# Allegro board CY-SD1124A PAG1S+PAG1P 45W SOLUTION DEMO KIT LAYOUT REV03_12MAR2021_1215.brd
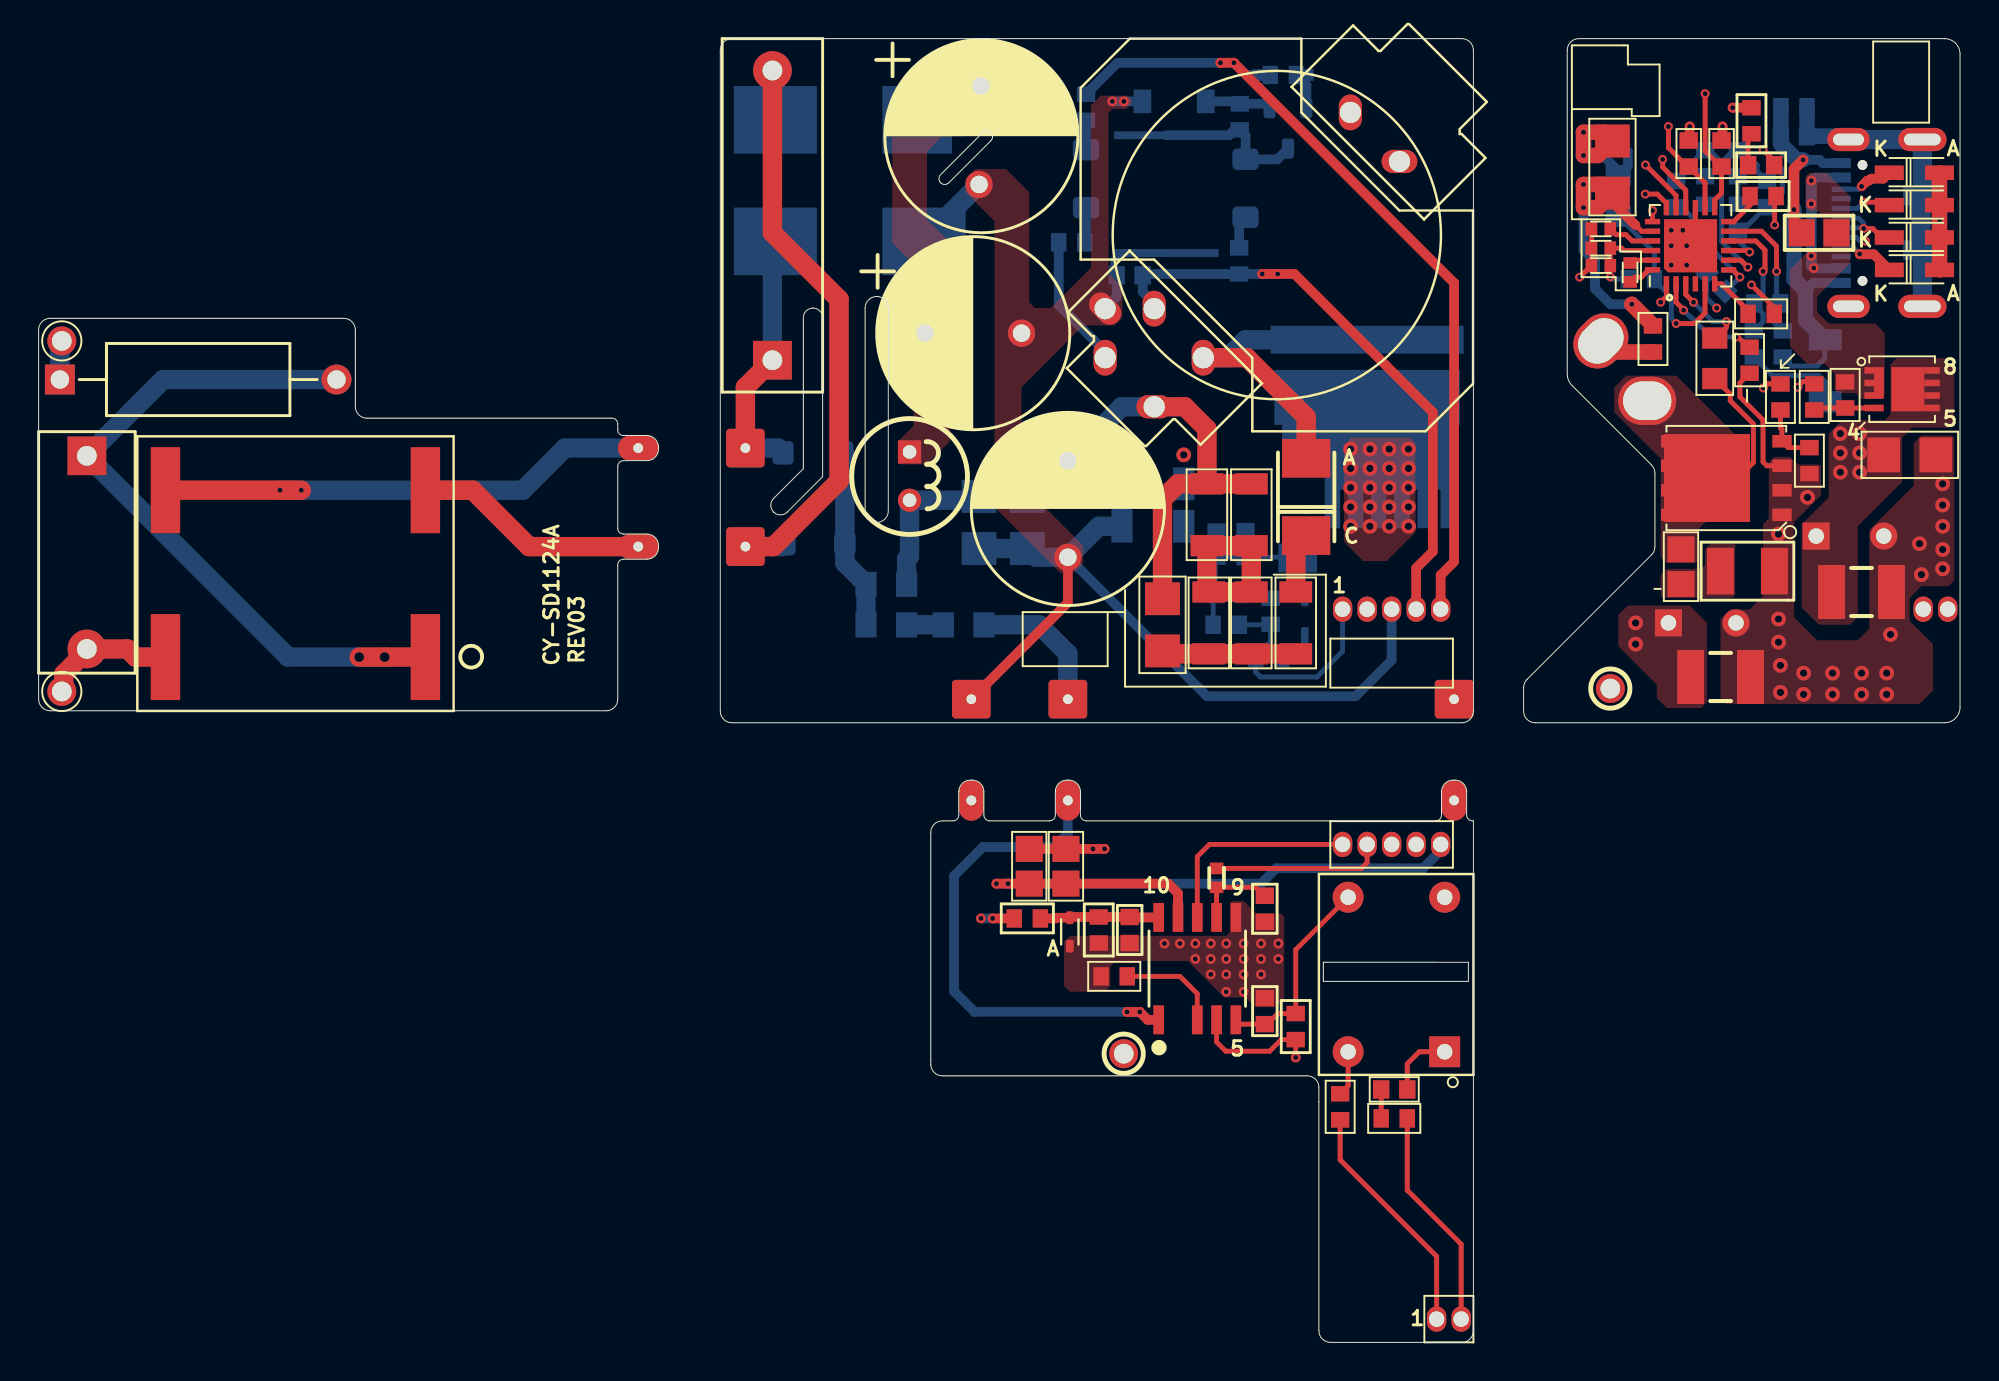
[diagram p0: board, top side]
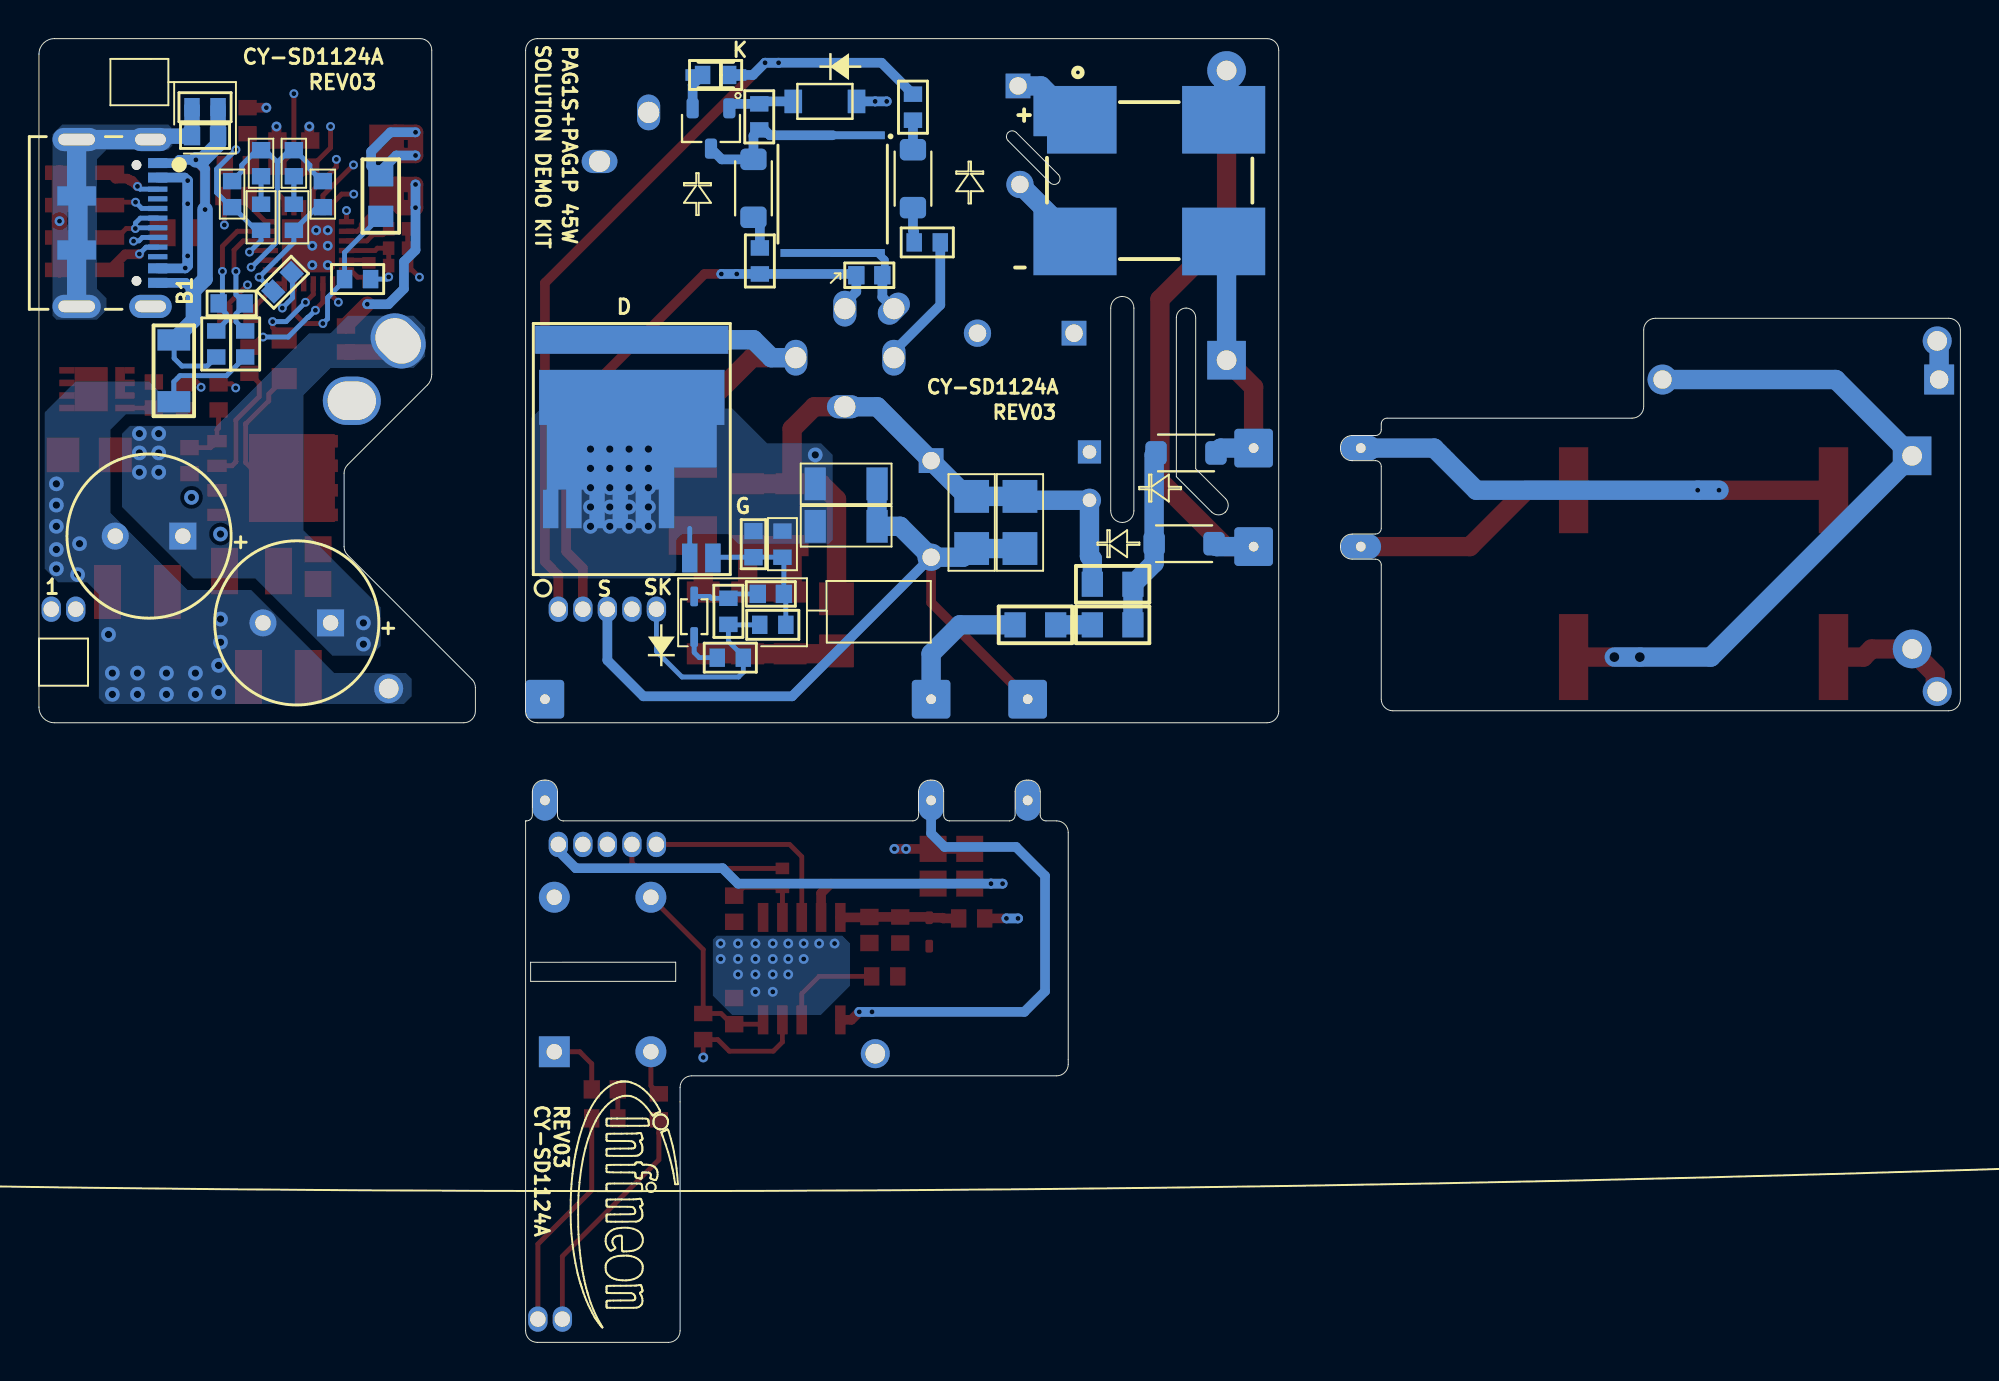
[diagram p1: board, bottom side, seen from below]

Outline 99.5 x 67.5 mm; copper layers: TOP, SIGNAL LAYER 1, SIGNAL LAYER 2, BOTTOM. Coordinates in mm from the lower left corner of the outline.
Outline path: 0,52.42 arc(0.18,52.84) 0.6,53.02 15.8,53.02 arc(16.22,52.84) 16.4,52.42 16.4,48.45 arc(16.58,48.03) 17,47.85 29.69,47.85 arc(29.9,47.76) 29.99,47.55 29.99,47.25 arc(30.08,47.04) 30.29,46.95 31.5,46.95 arc(31.92,46.77) 32.1,46.35 32.1,46.25 arc(31.92,45.83) 31.5,45.65 30.29,45.65 arc(30.08,45.56) 29.99,45.35 29.99,42.15 arc(30.08,41.94) 30.29,41.85 31.5,41.85 arc(31.92,41.67) 32.1,41.25 32.1,41.15 arc(31.92,40.73) 31.5,40.55 30.29,40.55 arc(30.08,40.46) 29.99,40.25 29.99,33.3 arc(29.81,32.88) 29.39,32.7 0.6,32.7 arc(0.18,32.88) 0,33.3 0,52.42 ; 35.3,66.9 arc(35.48,67.32) 35.9,67.5 73.7,67.5 arc(74.12,67.32) 74.3,66.9 74.3,32.68 arc(74.12,32.26) 73.7,32.08 35.9,32.08 arc(35.48,32.26) 35.3,32.68 35.3,66.9 ; 38.06,42.99 arc(37.92,43.34) 38.06,43.7 39.6,45.23 39.6,53.05 arc(39.75,53.4) 40.1,53.55 arc(40.45,53.4) 40.6,53.05 40.6,44.82 38.77,42.99 arc(38.42,42.84) 38.06,42.99 ; 42.8,53.55 arc(42.98,53.97) 43.4,54.15 arc(43.82,53.97) 44,53.55 44,43.05 arc(43.82,42.63) 43.4,42.45 arc(42.98,42.63) 42.8,43.05 42.8,53.55 ; 46.2,26.4 46.2,14.4 arc(46.38,13.98) 46.8,13.8 65.7,13.8 arc(66.12,13.62) 66.3,13.2 66.3,0.6 arc(66.48,0.18) 66.9,0 73.7,0 arc(74.12,0.18) 74.3,0.6 74.3,27 74.25,27 arc(74.04,27.09) 73.95,27.3 73.95,28.51 arc(73.77,28.93) 73.35,29.11 73.25,29.11 arc(72.83,28.93) 72.65,28.51 72.65,27.3 arc(72.56,27.09) 72.35,27 54.25,27 arc(54.04,27.09) 53.95,27.3 53.95,28.51 arc(53.77,28.93) 53.35,29.11 53.25,29.11 arc(52.83,28.93) 52.65,28.51 52.65,27.3 arc(52.56,27.09) 52.35,27 49.25,27 arc(49.04,27.09) 48.95,27.3 48.95,28.51 arc(48.77,28.93) 48.35,29.11 48.25,29.11 arc(47.83,28.93) 47.65,28.51 47.65,27.3 arc(47.56,27.09) 47.35,27 46.8,27 arc(46.38,26.82) 46.2,26.4 ; 46.71,60.46 48.89,62.64 arc(49.1,62.73) 49.31,62.64 arc(49.4,62.43) 49.31,62.21 47.14,60.04 arc(46.92,59.95) 46.71,60.04 arc(46.62,60.25) 46.71,60.46 ; 66.53,19.68 74.04,19.68 74.04,18.69 66.53,18.69 66.53,19.68 ; 76.9,33.9 arc(76.95,34.13) 77.08,34.33 83.52,40.77 arc(83.65,40.97) 83.7,41.2 83.7,45 arc(83.65,45.23) 83.52,45.43 79.39,49.56 arc(79.22,49.82) 79.16,50.12 79.16,66.9 arc(79.34,67.32) 79.76,67.5 98.7,67.5 arc(99.27,67.27) 99.5,66.7 99.5,32.88 arc(99.27,32.31) 98.7,32.08 77.5,32.08 arc(77.08,32.26) 76.9,32.68 76.9,33.9

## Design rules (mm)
constraint set DEFAULT: min track width 0.152
net group 400V: nets VDC_IN
net group AC: nets AC-IN-L AC-IN-N FUSE-IN N14642346
net group PRIMARY SIDE: nets PAG1P-AUXIN TXR-AUX-NPN-B1 TXR-AUX-NPN-E

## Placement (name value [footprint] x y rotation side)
BD1  -  [Z4DGP406L-HF]  42 60.15 90 bottom
C1  22uF  [CAPCC0805]  53.2 24.65 90 top
C2  100nF  [CAPCC1206]  48.7 42.45 270 bottom
C3  33uF  [CAPPRD600W60D1000H2150]  48.82 62.45 270 top
C4  22uF  [CAPCC0805]  51.3 24.65 90 top
C5  33uF  [CAPPRD600W60D1000H2150#2]  53.3 43.15 270 top
C6  100nF  [CAPCC1206]  51.2 42.45 270 bottom
C8  2.2uF  [CAP_5750]  58.4 59.45 270 bottom
C9  68pF  [CAPCC0603]  56.5 21.35 270 top
C10  1nF  [CAPCC1206]  58.2 37.15 270 top
C11  220pF  [CAPCC0603]  63.5 22.45 270 top
C12  1uF  [CAPCC0603]  63.5 17.15 90 top
C13  1nF  [CAPCC0603]  70.2 13.1 180 top
C14  1uF  [CAPCC0402]  80.9 57.65 180 top
C15  0.1uF  [CAPCC0402]  80.9 56.65 180 top
C16  4.7uF  [CAPCC0402]  80.9 55.75 180 top
C17  390pF  [CAPCC0603]  85.45 61.55 90 top
C18  0.1uF  [CAPCC0402]  82.41 55.4 270 top
C19  390pF  [CAPCC0603]  87.15 61.55 90 top
C20  10pF  [CAPCC0603]  89.5 59.45 90 bottom
C21  1nF  [CAPCC0603]  88 61.05 90 bottom
C22  47nF  [CAPCC0603]  86.3 61.05 90 bottom
C23  100pF  [CAPCC0603]  84.8 59.45 90 bottom
C24  100nF  [CC1210]  87.1 34.45 0 top
C25  10uF  [CAPCC0805]  92.2 57.45 180 top
C26  10uF  [CAPCC1206]  96.9 45.95 0 top
C27  10uF  [CAPCC1206]  81.5 60.85 90 top
C28  2.2nF  [CAPCC0603]  89.2 60.95 0 top
C29  2.2nF  [CAPCC0603]  86.89 54.89 135 bottom
C30  820pF  [CAPCC0805]  85.05 40.16 270 top
C31  0.1uF  [CAPCC0603]  89.52 53.79 0 bottom
C32  2200pF  [CAPCC0603]  90.9 62.45 0 bottom
C33  100nF  [CC1210]  94.4 38.85 0 top
C34  470uF  [CAPPRD350W60D800H1350P]  92.05 41.74 0 bottom
C35  470uF  [CAPPRD350W60D800H1350P]  84.4 37.25 0 bottom
C36  33pF  [CAPCC0603]  56.5 55.25 180 bottom
C37  10pF  [CAPCC0603]  62.5 41.33 90 bottom
C38  2.2nF  [CAPCC0603]  61.6 38.75 180 bottom
C39  33uF  [CAPPRD600W60D1000H2150#2]  48.4 52.25 0 top
CX1  0.068uF,310VAC  [BFC233820683]  2.5 40.9 270 top
CX2  0.068uF,310VAC  [R463I26804001M]  38 58.35 90 top
D1  BZT52C16-TP  [BZT52C12-TP_SOD123]  58.8 64.25 0 bottom
D2  S1ML R3G  [SODFL360X180X143L60X100N]  40.2 41.35 180 bottom
D3  RS1MSWF-7  [SODFL350X180X115L60X107N]  62.5 59.75 270 bottom
D4  S1ML R3G  [SODFL360X180X143L60X100N]  40.1 46.05 180 bottom
D5  BAT54XV2T1G  [BAT54XV2T1G_SOD523]  53.4 21.25 270 top
D6  RS2MA-13-F  [DIOC430X260X230L114]  65.64 43.77 90 top
D7  1N4148WS  [SODFL250X125X90L60X30N_1]  64.45 65.62 0 bottom
D8  DESD5V0S1BA-7  [DIO-SOD323]  97.14 60.56 0 top
D9  DESD5V0S1BA-7  [DIO-SOD323]  97.14 58.88 0 top
D10  DESD5V0S1BA-7  [DIO-SOD323]  97.14 57.2 0 top
D11  DESD5V0S1BA-7  [DIO-SOD323]  97.14 55.53 0 top
D12  BAT54J,115  [SODFL250X125X90L60X30N]  65.57 37.57 90 bottom
D13  RS1MSWF-7  [SODFL350X180X115L60X107N]  54.24 60.25 270 bottom
EF9  -  [EDGEFINGER]  36.6 46.3 0 top
EF10  -  [EDGEFINGER]  36.6 41.2 0 top
EF11  EDGEFINGER  [EDGEFINGER1]  31.05 41.2 90 top
EF12  EDGEFINGER  [EDGEFINGER1]  31.05 46.3 90 top
EF13  EDGEFINGER  [EDGEFINGER1]  53.3 28.06 180 top
EF14  -  [EDGEFINGER]  53.3 33.3 0 top
EF15  EDGEFINGER  [EDGEFINGER1]  48.3 28.06 180 top
EF16  -  [EDGEFINGER]  48.3 33.3 0 top
F1  2A Fuse  [FUSE_C310FH-2-RE-TR1-1]  1.1 49.85 0 top
J1  DX07S016JA3R1500  [JAE_DX07S016JA3R1500]  96.7 57.96 270 bottom
J2  -  [TMS-105-02-G-S-RA]  70.06 35.22 0 top
J3  PCBCOMPONENT  [PCBCOMPONENT5PIN]  70.06 25.78 0 top
J4  PCBCOMPONENT  [PCBCOMP2PIN]  73.03 1.21 0 top
J5  -  [TMS-102-02-G-S-RA]  98.23 35.22 180 bottom
L1  TEST_POINT  [TP-43R_S_2]  1.2 51.85 270 top
L3  22uH, 1.8A  [INDU_7447462220]  45.1 44.85 270 top
LF1  10mH, 1.2A  [CJ5094-CL]  13.3 39.8 270 top
N1  TEST_POINT  [TP-43R_S_1]  1.2 33.7 180 top
NOREF  -  []  2.79 56.69 0 top
NOREF#2  -  []  76.9 33.3 0 top
NOREF#3  -  []  17 47.85 90 top
NOREF#4  -  []  66.3 0.6 0 top
NOREF#5  -  []  16.4 52.42 0 top
NOREF#6  -  [unnamed#2]  73.3 28.06 180 top
NOREF#7  -  []  76.9 32.68 0 top
NOREF#8  -  []  0 33.3 0 top
NOREF#9  -  []  0.09 52.74 0 top
NOREF#10  -  []  35.9 32.08 90 top
NOREF#11  -  []  35.3 66.28 0 top
NOREF#12  -  []  0.6 32.7 90 top
NOREF#13  -  []  0 52.42 0 top
NOREF#14  -  []  73.7 0 90 top
NOREF#15  -  [unnamed#2]  73.3 33.3 0 top
NOREF#16  -  []  35.46 66.69 0 top
NOREF#17  -  []  93.79 32.11 0 top
NOREF#18  -  []  75.07 -1.08 0 top
NOREF#19  -  []  46.2 26.4 0 top
NOREF#20  -  []  29.39 32.7 90 top
NOREF#21  -  []  79.16 50.12 90 top
NOREF#22  -  []  145.31 -120.97 0 top
NOREF#23  -  []  96.88 32.08 90 top
NOREF#24  -  []  83.7 41.2 90 top
NOREF#25  -  []  79.16 66.9 0 top
NOREF#26  -  []  145.31 -120.97 0 top
NOREF#27  -  []  99.34 67.18 0 top
Q1  IGT60R070D1ATMA1  [IGT60R070D1]  68.8 46.25 180 bottom
Q2  PBSS8110T,215  [SOT23-3P95_240X100L40X44N]  64.7 62.85 0 bottom
Q3  BSC160N15NS5ATMA1  [TDSON8]  87.4 44.75 180 top
Q4  BSZ0902NSATMA1  [TSDSON65P330X330X110-8N_A]  96.5 49.35 0 top
R1  47K  [RESC0603]  61 41.33 270 bottom
R2  499K  [RESC0603]  55.7 18.95 0 top
R3  0.39R  [RESC1206]  57.7 42.25 180 bottom
R4  0.39R  [RESC1206]  57.7 44.45 180 bottom
R5  2.2E  [RESC0603]  62.17 55.99 270 bottom
R6  200K  [RESC0603]  62.2 63.45 90 bottom
R7  270K  [RESC0603]  51.2 21.95 180 top
R8  47 OHM  [RESC0805]  47.9 37.15 180 bottom
R9  47 OHM  [RESC0805]  43.9 37.15 180 bottom
R10  0E  [RESC0603]  64.46 65.62 0 bottom
R11  10K  [RESC0603]  54.9 21.35 90 top
R12  180K  [RESC1206]  62.8 42.85 270 top
R13  180K  [RESC1206]  62.8 37.25 270 top
R14  49.9E  [RESC1206]  65.1 37.25 270 top
R15  180K  [RESC1206]  60.5 42.85 270 top
R16  180K  [RESC1206]  60.6 37.25 270 top
R17  560E  [RESC0603]  63.8 37.85 90 bottom
R18  2K  [RESC0603]  65.1 16.35 90 top
R19  1K  [CAPCC0402]  61 24.05 90 top
R20  150E  [RESC0603]  70.2 11.6 180 top
R21  0E  [RESC0603]  67.4 12.2 90 top
R22  0E  [RESC0603]  83.6 51.95 270 top
R23  1E  [RESC0603]  90.2 48.95 270 top
R24  47K  [RESC0603]  91.7 45.65 90 top
R25  1.47M OHM  [RESC0603]  88 58.25 270 bottom
R26  147K  [RESC0603]  86.3 58.25 270 bottom
R27  0E  [RESC0603]  89.2 53.25 180 top
R28  0E  [RESC0603]  88.6 50.85 270 top
R29  9.09K  [RESC0805]  86.8 50.95 270 top
R30  47K  [RESC0603]  93.55 49.05 270 top
R31  2.2E  [RESC0603]  91.95 48.95 270 top
R32  1K  [RESC0603]  88.7 63.25 90 top
R33  100K  [RESC0603]  83 55.05 180 bottom
R34  1K  [RESC0603]  89.3 59.35 180 top
R35  20E  [1210]  88.49 39.93 180 top
R36  0E  [RESC0603]  90.9 63.95 180 bottom
R37  0E  [RESC0603]  88.82 51.69 270 bottom
R38  0E  [RESC0603]  90.32 51.69 270 bottom
R39  5m  [RESC1206]  92.52 50.3 270 bottom
R40  10E  [RESC0603]  63.7 35.45 0 bottom
R41  2.2E  [RESC0603]  53.5 56.95 180 bottom
R43  0E  [RESC0603]  54.24 63.95 90 bottom
R44  0E  [RESC0805]  43.9 39.25 180 bottom
R45  1K  [RESC0603]  61.5 37.15 180 bottom
RT1  100K  [RESC0805]  81.8 59.35 270 bottom
SEC1  TEST_POINT  [TP-43R_S_1]  83.3 48.75 90 top
SEC2  TEST_POINT  [TP-43R_S_1]  80.9 51.85 135 top
T1  RM8 CORE  [RM8]  64.12 57.33 270 top
T2  1:3  [RDL_R113426000ALT]  70.31 19.05 270 top
TP-P1  TEST_POINT  [TP-43R_S_1]  56.19 14.95 0 top
TP-S1  TEST_POINT  [TP-43R_S_1]  81.39 33.85 0 top
U1  PAG1P  [SOIC100P600X175-10N_CYPS]  60 19.35 90 top
U2  PAG1S  [QFN50P400X400X60-25T275X275N]  85.55 56.78 90 top

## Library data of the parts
BD1 = BR805D_2
C1 C2 C4 C6 C9-C33 C36-C38 CX1 CX2 = 0_0.01uF-50V-10%-X7R-0603
C3 C5 C34 C35 C39 = CAP_2
C8 = 0_0.01uF-50V-10%-X7R-0603: User Part Number: PN; Tolerance: TOL
D1 = DIODE SCHOTTKY_19
D2 D4 D7 = DIODE_15
D3 D13 = DIODE_17
D5 = DIODE SCHOTTKY_21
D6 = DIODE_13
D8-D11 = TVS DIODE_1
D12 = DIODE_18
EF9-EF16 = EDGEFINGER
F1 = Fuse 2
J1 = USB-PD_TYPE-C_8
J2 = CON6_0
J3 = CON6_1
J4 J5 = CON2
L1 N1 SEC1 SEC2 TP-P1 TP-S1 = TEST_POINT
L3 = INDUCTOR_PAG1S_1
LF1 = INDUCTOR IRON_8
Q1 = 2N6802_1
Q2 = 2N1070_1
Q3 Q4 = DMTH10H010LCT_5
R1 R2 R7-R11 R14 R17-R34 R36-R38 R40 R43-R45 = 330 ohm 5% 0805_0
R3-R6 R12 R13 R15 R16 R35 R39 R41 = RESISTOR
RT1 = RESISTOR VAR 2_4
T1 = PA5222NL_37
T2 = TRANSFORMER_13
U1 = PAG1P_3
U2 = PAG1S_11

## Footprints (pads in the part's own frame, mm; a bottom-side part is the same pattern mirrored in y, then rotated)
1210
  rect 1.397x2.413 smd: 1(-1.397,0) 2(1.397,0)
BAT54XV2T1G_SOD523
  custom 0.1x0.1 smd: A(0.735,0) C(-0.735,0)
BFC233820683
  rect 2x2 hole 1.02: 1(-5,0)
  round 2 hole 1.02: 2(5,0)
BZT52C12-TP_SOD123
  rect 0.914x1.219 smd: A(-1.638,0) K(1.638,0)
CAP_5750
  rect 0.406x5.41 smd: 1(-3.048,0) 2(3.048,0)
CAPCC0402
  rect 0.6x0.7 smd: 1(-0.49,0) 2(0.49,0)
CAPCC0603
  rect 0.85x0.95 smd: 1(-0.675,0) 2(0.675,0)
CAPCC0805
  rect 1.35x1.4 smd: 1(-0.9,0) 2(0.9,0)
CAPCC1206
  rect 1.7x1.8 smd: 1(-1.35,0) 2(1.35,0)
CAPPRD350W60D800H1350P
  rect 1.4x1.4 hole 0.8: 1(0,0)
  round 1.4 hole 0.8: 2(3.5,0)
CAPPRD600W60D1000H2150
  rect 1.28x1.28 hole 0.904: 1(-2.6,-0.02)
  round 1.412 hole 0.904: 2(2.5,-0.12)
CAPPRD600W60D1000H2150#2
  rect 1.28x1.28 hole 0.904: 1(-2.5,0)
  round 1.412 hole 0.904: 2(2.5,0)
CC1210
  rect 1.397x2.794 smd: 1(-1.55,0) 2(1.55,0)
CJ5094-CL
  rect 4.45x1.52 smd: 1(4.32,6.73) 2(-4.32,6.73) 3(-4.32,-6.73) 4(4.32,-6.73)
DIO-SOD323
  rect 1.5x0.75 smd: A(1.3,0) C(-1.3,0)
DIOC430X260X230L114
  rect 2x2.5 smd: A(2,0) C(-2,0)
EDGEFINGER
  custom 0.5x0.5 hole 1.7x1.4: 1(0,0)
EDGEFINGER1
  oval 1.3x2.1 hole 0.508: 1(0,0)
FUSE_C310FH-2-RE-TR1-1
  rect 1.55x1.55 hole 0.95: 1(0,0)
  round 1.55 hole 0.95: 2(14.326,0)
IGT60R070D1
  custom 0.362x0.362 smd: D(0,5.66)
  rect 0.8x1.5 smd: G(4.2,-5.64) SK(3,-5.64)
  custom 2.05x2.05 smd: S(0,0)
INDU_7447462220
  rect 1.2x1.2 hole 0.7: 1(-1.25,0)
  round 1.2 hole 0.7: 2(1.25,0)
JAE_DX07S016JA3R1500
  round 0.5 hole 0.6 unplated: (-3,2.25)
  oval 0.5x0.5 hole 0.85x0.6 unplated: (3,2.25)
  rect 0.52x1 smd: A1(-3.1,3.35) A4(-2.35,3.35) B1(3.1,3.35) B4(2.35,3.35)
  rect 0.27x1 smd: A5(-1.75,3.35) A6(-0.25,3.35) A7(0.75,3.35) A8(1.75,3.35) B5(1.25,3.35) B6(0.25,3.35) B7(-0.75,3.35) B8(-1.25,3.35)
  oval 1.2x2.2 hole 0.6x1.6: MH1(-4.32,2.975) MH4(4.32,2.975)
  oval 1.2x2.5 hole 0.6x1.9: MH2(-4.32,-0.85) MH3(4.32,-0.85)
  rect 1x2 smd: S1(-1.4,-0.85) S2(1.4,-0.85)
PCBCOMP2PIN
  oval 1x1.308 hole 0.8: 1(-0.635,0) 2(0.635,0)
PCBCOMPONENT5PIN
  oval 1x1.308 hole 0.8: 1(-2.54,0) 2(-1.27,0) 3(0,0) 4(1.27,0) 5(2.54,0)
QFN50P400X400X60-25T275X275N
  rect 0.79x0.28 smd: 1(-1.97,1.25) 2(-1.97,0.75) 3(-1.97,0.25) 4(-1.97,-0.25) 5(-1.97,-0.75) 6(-1.97,-1.25) 13(1.97,-1.25) 14(1.97,-0.75) 15(1.97,-0.25) 16(1.97,0.25) 17(1.97,0.75) 18(1.97,1.25)
  rect 0.28x0.79 smd: 7(-1.25,-1.97) 8(-0.75,-1.97) 9(-0.25,-1.97) 10(0.25,-1.97) 11(0.75,-1.97) 12(1.25,-1.97) 19(1.25,1.97) 20(0.75,1.97) 21(0.25,1.97) 22(-0.25,1.97) 23(-0.75,1.97) 24(-1.25,1.97)
  custom 0.687x0.687 smd: 25(0,0)
R463I26804001M
  rect 2x2 hole 1.02: 1(-7.5,0)
  round 2 hole 1.02: 2(7.5,0)
RDL_R113426000ALT
  rect 1.6x1.6 hole 0.8: 1(4,2.5)
  round 1.6 hole 0.8: 2(4,-2.5) 3(-4,2.5) 4(-4,-2.5)
RESC0603
  rect 0.8x0.95 smd: 1(-0.675,0) 2(0.675,0)
RESC0805
  rect 1.1x1.3 smd: 1(-1.05,0) 2(1.05,0)
RESC1206
  rect 1.1x1.7 smd: 1(-1.6,0) 2(1.6,0)
RM8
  oval 1.85x1.2 hole 1.1: (-6.35,3.81) 1(6.35,-8.89) 5(3.81,-6.35) 6(6.35,-3.81)
  oval 1.2x1.85 hole 1.1: (-3.81,6.35) 2(8.89,-6.35)
  oval 1.2x1.85 hole 1.1 rot 135: 3(3.81,-8.89)
SODFL250X125X90L60X30N
  custom 0.1x0.1 smd: A(1.05,0) C(-1.05,0)
SODFL250X125X90L60X30N_1
  rect 1.05x0.6 smd: A(1.05,0) C(-1.05,0)
SODFL350X180X115L60X107N
  custom 0.278x0.278 smd: A(1.5,0) C(-1.5,0)
SODFL360X180X143L60X100N
  custom 0.278x0.278 smd: A(1.55,0) C(-1.55,0)
SOIC100P600X175-10N_CYPS
  rect 1.5x0.55 smd: 1(-2.65,2) 3(-2.65,0) 4(-2.65,-1) 5(-2.65,-2) 6(2.65,-2) 7(2.65,-1) 8(2.65,0) 9(2.65,1) 10(2.65,2)
SOT23-3P95_240X100L40X44N
  custom 0.158x0.158 smd: 1(-0.95,-1.045) 2(0.95,-1.045) 3(0,1.045)
TDSON8
  rect 1x0.65 smd: 1(-2.88,1.905) 2(-2.88,0.635) 3(-2.88,-0.635) 4(-2.88,-1.905) 5(2.88,-1.905) 6(2.88,-0.635) 7(2.88,0.635) 8(2.88,1.905)
TMS-102-02-G-S-RA
  oval 1x1.308 hole 0.8: 1(-0.635,2.74) 2(0.635,2.74)
TMS-105-02-G-S-RA
  oval 1x1.308 hole 0.8: 1(-2.54,2.74) 2(-1.27,2.74) 3(0,2.74) 4(1.27,2.74) 5(2.54,2.74)
TP-43R_S_1
  round 1.5 hole 1.02: 1(0,0)
TP-43R_S_2
  round 1.5 hole 1.02: 1(0,0)
TSDSON65P330X330X110-8N_A
  rect 0.5x0.34 smd: 1(-1.7,0.975) 2(-1.7,0.325) 3(-1.7,-0.325)
  rect 1x0.34 smd: 4(-1.45,-0.975)
  rect 0.8x0.34 smd: 5(1.55,-0.975) 6(1.55,-0.325) 7(1.55,0.325) 8(1.55,0.975)
unnamed#2
  oval 1.3x2.1 hole 0.508: 1(0,0)
Z4DGP406L-HF
  custom 0.875x0.875 smd: 1(3.15,3.85)
  rect 3.5x4.3 smd: 2(3.15,-3.85) 3(-3.15,-3.85) 4(-3.15,3.85)

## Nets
VBUS-CTRL-G: Q4.4 R30.2 R31.2
VBUS_C: C25.1 J1.A4 J1.B4(VBUS_3) Q4.1 Q4.2 Q4.3(S#3) R30.1 U2.18
VBUS_IN: C24.1 C26.1 C33.1 C34.1 C35.1 Q4.5 Q4.6 Q4.7 Q4.8 R22.2 SEC2.1
VDDD: C15.1 C16.1 R33.2 U2.22
AC-IN-L: F1.1 L1.1
AC-IN-N: CX1.2 LF1.4 N1.1
BD-OUT: BD1.1(DC OUT PLUS) C3.1 C39.1 L3.1
FUSE-IN: CX1.1 F1.2 LF1.1
PAG1P-AUXIN: D7.C J2.5 R10.1 R43.2
PAG1P-AUXIN_16126649: C1.1 C4.1 J3.5 U1.9
PAG1P-CS: C11.1 R19.1 U1.7
PAG1P-OVP-AUX: C9.1 D5.C(K) R7.1 R11.2 U1.10
PAG1P-PULSEIN: R18.1 T2.3 U1.4
PAG1P-RT: R2.2 U1.3
PAG1P-SS: C12.1 R18.2 T2.4 U1.5
PAG1P-START-RD: D2.C D4.C R9.2 R44.2
PAG1P-START-RR: R8.2 R9.1
PAG1P-VDD700: EF14.1 R8.1
PAG1P-VDD700_16126801: EF13.1 U1.1(VDD700)
PAG1S-CC1: C17.1 D8.C J1.A5 U2.14
PAG1S-CC2: C19.1 D11.C J1.B5 U2.13
PAG1S-CC-COMP: C23.1 C29.1 R26.2 U2.7
PAG1S-CC-COMP-RC: C22.1 R26.1
PAG1S-CC-RC: C29.2 R34.1
PAG1S-CSN: C31.1 R37.1 U2.10
PAG1S-CSP: C31.2 R38.1 U2.11
PAG1S-CV-COMP-RC: C21.1 R25.1
PAG1S-DM-GPIO4: D9.C J1.A7 J1.B7 U2.16
PAG1S-DP-GPIO5: D10.C J1.A6 J1.B6 U2.17
PAG1S-EA-OUT: C20.2 C21.2 C22.2 C23.2 U2.8
PAG1S-FB: C20.1 C28.2 R25.2 U2.9
PAG1S-FB-RC: C28.1 R32.1
PAG1S-GPIO0: R33.1 RT1.2 U2.5
PAG1S-GPIO1: R27.2 U2.6
PAG1S-GPIO3: R34.2 U2.12
PAG1S-SR-GDRV: R23.1 U2.1
PAG1S-SR-SENSE: R29.1 U2.3
PAG1S-SR-VSS: R28.1 U2.2
PAG1S-VBUS-IN: C27.1 R22.1 R32.2 U2.20
PAG1S-VCCD: C14.1 U2.21
PAG1S-XRES: U2.4(XRES)
PE_GND: BD1.4 C2.2 C3.2 C5.2 C6.2 C8.2 C36.2 C39.2 D1.A EF16.1 J2.3 R3.2 R4.2 T1.3
PE_GND1: C1.2 C4.2 C9.2 C11.2 C12.2 D5.A J3.3 R2.1 R11.1 U1.6
PE_GND_2: EF15.1 TP-P1.1
PRI-FET-D: D6.A Q1.D T1.6(IN2)
PRI-FET-GATE: J2.1 R17.1 R40.1 R45.1
PRI-FET-GATE_16126801: J3.1 U1.8
PRI-FET-S: C37.2 J2.2 Q1.S Q1.SK R1.1 R3.1 R4.1
PRI-FET-S_16126973: J3.2 R19.2
PULSE-TXR-SEC1: J5.1 R27.1
PULSE-TXR-SEC1_15963342: J4.2 R20.1
PULSE-TXR-SEC2: J4.1 R21.1
SE_GND: C14.2 C15.2 C16.2 C17.2 C19.2 C24.2 C26.2 C27.2 C33.2 C34.2 C35.2 J5.2 Q3.1 Q3.2 Q3.3(S#3) R24.1 R28.2 R35.1 R37.2 R39.2 RT1.1 TP-S1.1 U2.15 U2.25
SR-FET-D: C30.1 Q3.5 Q3.6 Q3.7 Q3.8 R29.2 SEC1.1
SR-FET-G: Q3.4 R23.2 R24.2
SR-FET-SNUB: C30.2 R35.2
TX-AUX-RD1: D3.A R5.1
TX-AUX-RD2: D13.A R41.1
TXR-AUX1: C36.1 J2.4 R5.2 T1.5
TXR-AUX1_16126607: J3.4 R7.2
TXR-AUX-NPN-B1: D1.K Q2.1 R6.2
TXR-AUX-NPN-C1: C8.1 D3.C Q2.3 R6.1
TXR-AUX-NPN-E: D7.A Q2.2(E) R10.2
TYPE-C_GND: C25.2 C32.1 D8.A D9.A D10.A D11.A J1.A1 J1.B1 R36.2 R38.2 R39.1
VCLAMP-RCD: C10.2 R13.2 R14.2 R16.2
VDC_IN: C2.1 C5.1 C6.1 C10.1 L3.2 R12.1 R15.1 R44.1 T1.2
N14642334: BD1.3 CX2.1 D4.A EF9.1
N14642346: BD1.2 CX2.2 D2.A EF10.1
N15949532: C18.2 U2.24
N15949534: C18.1 U2.23
N15949698: C32.2 J1.MH1 J1.MH2 J1.MH3 J1.MH4 J1.S1 J1.S2 R36.1
N15949882: R31.1 U2.19
N15963322: R21.2 T2.2
N15963346: C13.2 R20.2
N15963350: C13.1 T2.1
N15983010: R12.2 R13.1 R15.2 R16.1
N15985596: C38.1 D12.A R17.2
N16013994: C37.1 C38.2 Q1.G R1.2 R45.2
N16032372: D6.C R14.1
N16078751: D13.C R43.1
N16079880: R41.2 T1.1
N16095646: EF11.1 LF1.2
N16095654: EF12.1 LF1.3
N16166937: D12.C R40.2

Pads without a net: J1 A8 B8; NOREF#6 1; NOREF#15 1

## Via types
v1: diameter 0.508, hole 0.254, TOP to BOTTOM, 58 vias
v2: diameter 0.762, hole 0.381, TOP to BOTTOM, 51 vias
v3: diameter 0.457, hole 0.254, TOP to BOTTOM, 30 vias
v4: diameter 0.762, hole 0.508, TOP to BOTTOM, 2 vias

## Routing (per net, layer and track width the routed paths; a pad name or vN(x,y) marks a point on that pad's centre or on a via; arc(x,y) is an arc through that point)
VBUS-CTRL-G: length 3.1
  TOP w0.254: R31.2 92.05,48.38 R30.2 95.05,48.38
VBUS_C: length 20.1
  TOP w0.254: U2.18 84.3,58.98 83.82,59.45 v3(83.2,59.45)
  SIGNAL LAYER 2 w0.35: v3(83.2,59.45) 89.2,59.45 91.8,56.85 v1(91.8,56.25) 91.8,55.75 v1(91.93,55.62)
  BOTTOM w0.5: J1.B4 91.94,55.61 v1(91.93,55.62) ; J1.A4 91.96,60.31 v1(91.8,60.15)
  BOTTOM w0.55: v1(91.93,55.62) 91.8,55.75 v1(91.8,56.25) v1(91.8,58.95) v1(91.8,60.15)
VBUS_IN: length 2.9
  TOP w0.8: R22.2 81.47,51.28 SEC2.1
  vias: v2(82.7,37.25) v2(82.7,36.15) v2(93.3,47.05) v2(93.3,46.05) v2(93.3,45.05) v2(94.3,47.05) v2(94.3,46.05) v2(94.3,45.05)
VDDD: length 4.7
  TOP w0.254: U2.22 82.1,56.53 81.98,56.65 C15.1 C16.1 v3(81.39,55.16)
  BOTTOM w0.254: v3(81.39,55.16) 81.5,55.05 R33.2
AC-IN-L: length 2
  BOTTOM w1: F1.1 1.1,51.75 L1.1
AC-IN-N: length 7
  TOP w1: N1.1 1.3,33.8 1.3,34.6 2.5,35.8 CX1.2 4.6,35.9 5.02,35.48 LF1.4
BD-OUT: length 3.7
  BOTTOM w1: BD1.1 47.6,65.05 C3.1
FUSE-IN: length 37.7
  TOP w1: v4(16.6,35.48) v4(17.92,35.48) LF1.1
  BOTTOM w1: F1.2 6.45,49.85 CX1.1 12.92,35.48 v4(16.6,35.48) v4(17.92,35.48)
PAG1P-AUXIN: length 44.5
  TOP w0.5: v1(61.2,66.25) v1(61.9,66.25) 73.3,54.85 73.3,40.42 72.6,39.72 J2.5
  BOTTOM w0.5: R43.2 55.87,66.25 v1(61.2,66.25) v1(61.9,66.25) 62.53,65.62 D7.C R10.1
PAG1P-AUXIN_16126649: length 34.9
  TOP w0.5: U1.9 59,23.25 58.5,23.75 C1.1 C4.1 v1(50.2,23.75) v1(49.6,23.75)
  BOTTOM w0.5: J3.5 72.6,25.46 71.7,24.55 64.1,24.55 63.3,23.75 v1(50.2,23.75) v1(49.6,23.75)
PAG1P-CS: length 4.2
  TOP w0.254: U1.7 R19.1 63.02,23.56 63.45,23.13 C11.1
PAG1P-OVP-AUX: length 6.2
  TOP w0.5: U1.10 56.52,22 C9.1 54.9,22.03 R11.2 53.44,22.02 D5.C 52.71,21.99 52.68,21.95 R7.1
PAG1P-PULSEIN: length 20.5
  TOP w0.25: v1(65.1,14.75) R18.1 64.35,15.68 63.75,15.08 61.47,15.08 61,15.55 U1.4
  SIGNAL LAYER 2 w0.25: T2.3 70.82,21.05 66.8,21.05 65.7,19.95 65.7,15.35 v1(65.1,14.75)
PAG1P-RT: length 5.3
  TOP w0.25: U1.3 60,18.05 59.1,18.95 R2.2
PAG1P-SS: length 10.6
  TOP w0.25: U1.5 62.23,16.47 C12.1 63.62,16.47 64.17,17.03 R18.2 65.1,20.33 T2.4
PAG1P-START-RD: length 9.4
  BOTTOM w1: R9.2 R44.2 41.75,40.35 D2.C 41.75,45.95 D4.C
PAG1P-START-RR: length 1.9
  BOTTOM w1: R9.1 R8.2
PAG1P-VDD700: length 7.3
  BOTTOM w1: R8.1 51.81,37.15 53.3,35.66 EF14.1
PAG1P-VDD700_16126801: length 26.4
  TOP w0.5: v1(56.36,17.11) v1(57.02,17.11) 57.43,16.7 U1.1
  BOTTOM w0.5: EF13.1 53.3,26.35 52.6,25.65 48.9,25.65 47.4,24.15 47.4,18.18 48.47,17.11 v1(56.36,17.11) v1(57.02,17.11)
PAG1S-CC1: length 23.7
  TOP w0.254: v3(84.4,62.95) 84.4,61.85 85.38,60.87 C17.1 86.3,60.03 U2.14
  TOP w0.5: D8.C 95.53,60.25 94.92,60.25 94.85,60.2 94.82,60.19 94.78,60.15 94.73,60.15 94.7,60.14 94.69,60.14 v3(94.4,59.85)
  SIGNAL LAYER 2 w0.254: v3(94.4,59.85) 94.76,60.21 94.76,60.24 95.01,60.49 95.09,60.61 95.11,60.66 95.13,60.67 95.13,60.68 95.2,60.75 95.2,63.35 93.9,64.65 87.5,64.65 86.7,63.85 85.3,63.85 v3(84.4,62.95)
  BOTTOM w0.25: J1.A5 94.26,59.71 v3(94.4,59.85)
PAG1S-CC2: length 28.7
  TOP w0.254: U2.13 86.8,59.15 87.15,59.5 C19.1 87.1,60.87 86.3,61.68 v3(86.3,64.65)
  TOP w0.5: v3(94.3,56.35) 94.3,56.35 94.32,56.33 95.04,56.33 D11.C
  SIGNAL LAYER 2 w0.254: v3(94.3,56.35) 95.4,56.35 95.9,56.85 95.9,63.85 94.4,65.35 87,65.35 v3(86.3,64.65)
  BOTTOM w0.25: J1.B5 93.94,56.71 93.98,56.67 93.99,56.67 94.18,56.48 94.18,56.47 v3(94.3,56.35)
PAG1S-CC-COMP: length 7
  TOP w0.254: v3(88.1,55.15) 87.72,55.53 U2.7
  BOTTOM w0.254: C23.1 85.1,58.77 R26.2 86.3,56.95 v3(88.1,55.15) 87.37,54.42 C29.1
PAG1S-CC-COMP-RC: length 1.5
  BOTTOM w0.254: 86.3,58.93 86.3,60.38
PAG1S-CC-RC: length 9.6
  TOP w0.254: v3(89.9,57.85) 89.9,59.28 R34.1
  SIGNAL LAYER 2 w0.254: v3(89.9,57.85) 89,57.85 86.9,55.75 v3(86.9,53.55)
  BOTTOM w0.254: C29.2 86.38,55.33 86.38,54.07 v3(86.9,53.55)
PAG1S-CSN: length 6.9
  TOP w0.254: v3(89.3,55.45) 89.4,55.55 89.4,56.55 88.92,57.03 88.35,57.03 U2.10
  BOTTOM w0.254: R37.1 89.3,52.84 89.3,53.25 88.85,53.7 C31.1 89.3,54.25 v3(89.3,55.45)
PAG1S-CSP: length 7.7
  TOP w0.254: U2.11 89.22,57.53 90,56.75 v3(90,55.45)
  BOTTOM w0.254: R38.1 89.8,52.89 89.8,53.25 90.2,53.65 C31.2 90,53.99 v3(90,55.45)
PAG1S-CV-COMP-RC: length 1.4
  BOTTOM w0.254: R25.1 C21.1
PAG1S-DM-GPIO4: length 22.9
  TOP w0.25: D9.C 95.68,59.03 v3(94.5,59.03)
  TOP w0.254: U2.16 85.3,59.65 84.1,60.85 v3(84.1,61.25)
  SIGNAL LAYER 2 w0.254: v3(94.6,57.01) 95.12,57.01 95.3,57.2 95.3,58.78 95.05,59.03 v3(94.5,59.03) 93.92,59.03 92.7,60.25 92.7,60.85 91.2,62.35 89,62.35 87.9,61.25 v3(84.1,61.25)
  BOTTOM w0.25: J1.A7 94.14,57.21 94.32,57.03 94.59,57.03 v3(94.6,57.01) ; J1.B7 94.17,58.71 v3(94.5,59.03)
PAG1S-DP-GPIO5: length 19.8
  TOP w0.25: v3(94.51,57.67) 94.98,57.67 95.45,57.2 D10.C
  TOP w0.254: U2.17 84.8,59.38 v3(83.21,60.96)
  SIGNAL LAYER 2 w0.254: v3(94.51,57.67) 93.98,57.67 92.1,59.55 90.4,59.55 89.6,60.35 83.82,60.35 v3(83.21,60.96)
  BOTTOM w0.25: J1.A6 94.25,58.21 94.5,57.96 94.5,57.68 v3(94.51,57.67) 94.5,57.67 94.46,57.71 J1.B6
PAG1S-EA-OUT: length 14
  TOP w0.254: U2.8 88.15,56.03 v3(88.51,55.67)
  BOTTOM w0.254: 87.15,61.1 87.77,61.72 C21.2 88.23,61.72 89,60.95 89,60.62 C20.2 ; 87.15,61.1 87.15,57 88.48,55.67 v3(88.51,55.67) ; 87.15,61.1 86.53,61.73 C22.2 86.25,61.73 85.47,60.95 85.47,60.75 84.85,60.12 C23.2
PAG1S-FB: length 9.3
  TOP w0.254: U2.9 88.52,56.53 v3(88.6,56.45) ; C28.2 89.87,61.18 v3(89.3,61.75)
  BOTTOM w0.254: v3(88.6,56.45) 88,57.05 R25.2 88.25,57.58 89.45,58.77 C20.1 89.55,58.77 90.3,59.53 90.3,59.56 90.31,59.56 90.31,60.69 90.3,60.69 90.3,60.75 v3(89.3,61.75)
PAG1S-FB-RC: length 1.7
  TOP w0.254: C28.1 88.52,62.4 88.7,62.58
PAG1S-GPIO0: length 10
  TOP w0.254: v3(84.8,52.75) 85.75,52.75 86.3,53.3 U2.5
  BOTTOM w0.254: v3(84.8,52.75) 84.56,52.99 84.56,54.09 84.49,54.15 84.49,54.16 83.67,54.98 R33.1 83.67,56.42 RT1.2
PAG1S-GPIO1: length 2.5
  TOP w0.254: R27.2 88.53,53.42 87.14,54.81 U2.6
PAG1S-GPIO3: length 1.9
  TOP w0.254: U2.12 87.78,58.03 88.63,58.88 R34.2
PAG1S-SR-GDRV: length 9.9
  TOP w0.254: R23.1 89.52,49.63 v3(89.31,49.41) ; v3(84,53.85) 84.3,54.15 U2.1
  SIGNAL LAYER 2 w0.254: v3(84,53.85) 84,52.65 87.24,49.41 v3(89.31,49.41)
PAG1S-SR-SENSE: length 4.4
  TOP w0.254: R29.1 86.85,52 87.4,52.55 v3(87.4,52.85) ; v3(85.7,53.85) 85.3,54.25 U2.3
  BOTTOM w0.254: v3(85.7,53.85) 86.7,52.85 v3(87.4,52.85)
PAG1S-SR-VSS: length 5.8
  TOP w0.254: R28.1 88.53,51.53 88,52.05 v3(87.9,52.05) ; U2.2 84.8,53.85 85.2,53.45 85.2,53.44 v3(85.18,53.44)
  BOTTOM w0.254: v3(87.9,52.05) 86.6,52.05 85.58,53.07 85.55,53.07 v3(85.18,53.44)
PAG1S-VBUS-IN: length 29
  TOP w0.254: U2.20 83.01,57.53 82.69,57.84
  TOP w0.5: R32.2 v1(87.73,63.92) ; C27.1 81.5,59.04 82.69,57.84
  TOP w0.8: R22.1 83.6,52.65 v1(82.5,53.75) ; C27.1 80.75,58.75 v1(80,58.75) v1(80,59.95) 81.05,59.95 C27.1
  SIGNAL LAYER 2 w0.5: v1(87.73,63.92) 88.1,63.55 88.1,62.55 87.6,62.05 82.1,62.05 v1(80,59.95)
  BOTTOM w0.5: v1(80,59.95) v1(80,58.75) 80,56.55 80.6,55.95 80.6,54.55 81.4,53.75 v1(82.5,53.75)
PAG1S-VCCD: length 2.4
  TOP w0.254: C14.1 81.69,57.35 82.2,57.35 82.52,57.03 U2.21
PE_GND: length 54.4
  TOP w0.5: C5.2 53.3,38.3 EF16.1
  BOTTOM w0.4: C8.2 58.4,56.41 56.06,56.41 55.7,56.04 55.7,55.37 C36.2
  BOTTOM w0.5: C5.2 60.5,33.45 68.2,33.45 70.06,35.32 J2.3 ; T1.3 55.83,54.12 C36.2 ; D1.A v1(56.2,64.25) v1(55.6,64.25)
  BOTTOM w1: BD1.4 45.85,57.1 C3.2 ; R4.2 R3.2 54.9,42.25 C5.2 51.65,40.65 C6.2 C2.2
PE_GND1: length 10.6
  TOP w0.5: v1(55.2,25.55) v1(54.6,25.55) C1.2 C4.2
  SIGNAL LAYER 1 w0.5: J3.3 70.06,25.42 69.15,24.5 64.1,24.5
  vias: v1(58.3,20.65) v1(59.1,20.65) v1(59.9,20.65) v1(59.9,19.85) v1(60.7,20.65) v1(60.7,19.85) v1(60.7,19.05) v1(61.5,20.65) v1(61.5,19.85) v1(61.5,19.05) v1(61.5,18.15) v1(62.4,20.65) v1(62.4,19.85) v1(62.4,19.05) v1(62.4,18.15) v1(63.3,20.65) v1(63.3,19.85) v1(63.3,19.05) v1(64.2,20.65) v1(64.2,19.85)
PE_GND_2: length 18.3
  SIGNAL LAYER 1 w0.5: EF15.1 48.3,24.75 47.7,24.15 47.7,20.96 53.71,14.95 TP-P1.1
PRI-FET-D: length 17.6
  TOP w1: D6.A 65.64,47.91 62.57,50.98 T1.6
  BOTTOM w1: Q1.D 62.5,51.91 61.57,50.98 T1.6
PRI-FET-GATE: length 11.8
  BOTTOM w0.25: J2.1 67.53,35.78 66.2,34.45 63.27,34.45 63.02,34.7 R40.1 63.02,35.53 63.8,36.3 R17.1 63.77,37.15 R45.1
PRI-FET-GATE_16126801: length 10.9
  TOP w0.25: U1.8 60,25.15 60.63,25.78 J3.1
PRI-FET-S: length 15.9
  SIGNAL LAYER 1 w0.5: v2(59.3,45.95) 62.49,45.95 68.79,39.64 J2.2
  BOTTOM w0.25: Q1.SK 65.8,42.15 ; 68.39,45.85 Q1.S
  vias: v2(67.94,46.25) v2(67.94,45.25) v2(67.94,44.25) v2(67.94,43.25) v2(67.94,42.25) v2(68.94,46.25) v2(68.94,45.25) v2(68.94,44.25) v2(68.94,43.25) v2(68.94,42.25) v2(69.94,46.25) v2(69.94,45.25) v2(69.94,44.25) v2(69.94,43.25) v2(69.94,42.25) v2(70.94,46.25) v2(70.94,45.25) v2(70.94,44.25) v2(70.94,43.25) v2(70.94,42.25)
PRI-FET-S_16126973: length 8.9
  TOP w0.254: J3.2 68.79,24.84 68.5,24.54 R19.2
PULSE-TXR-SEC1: length 23.5
  TOP w0.254: R27.1 89.88,53.58 v3(88.7,54.75)
  SIGNAL LAYER 2 w0.254: v3(88.7,54.75) 96.6,46.85 96.6,39.49 97.14,38.95 98.03,38.95 98.86,38.11 J5.1
PULSE-TXR-SEC1_15963342: length 11.5
  TOP w0.254: J4.2 73.67,5.08 70.88,7.88 R20.1
PULSE-TXR-SEC2: length 12.4
  TOP w0.254: R21.1 67.4,10.84 67.4,9.45 72.4,4.45 J4.1
SE_GND: length 31.1
  TOP w0.254: C14.2 C15.2 C16.2 79.81,55.15 v3(79.8,55.15) ; Q3.3 89.5,45.39 89.3,45.59 89.3,47.76 88.1,48.96 88.1,49.68 R28.2 ; U2.25 85.8,57.03 U2.15
  TOP w0.5: C19.2 87.2,62.27 v1(87.2,62.95) ; v1(85.5,62.95) 85.5,62.27 C17.2
  TOP w0.8: C27.2 80.75,61.45 v1(80,61.45) v1(80,62.65) 81.05,62.65 C27.2
  SIGNAL LAYER 1 w0.5: 97.6,39.85 97.59,39.84 J5.2
  BOTTOM w0.254: R37.2 89.79,50.05 92.2,50.05 92.52,49.73 R39.2
  BOTTOM w0.5: v1(80,62.65) 81.3,62.65 82.3,61.65 82.3,60.9 RT1.1 81.8,60.65 81,61.45 v1(80,61.45)
  vias: v1(84.55,57.58) v1(84.55,56.78) v1(84.55,55.78) v1(85.15,57.58) v1(85.35,56.78) v1(85.35,55.78) v2(90.1,41.85) v2(90.1,37.45) v2(90.1,36.25) v2(90.2,35.05) v2(90.2,33.65) v2(91.4,34.65) v2(91.4,33.55) v2(91.6,43.75) v2(92.9,34.65) v2(92.9,33.55) v2(94.4,34.65) v2(94.4,33.55) v2(95.7,34.65) v2(95.7,33.55) v2(95.9,36.65) v2(97.4,41.35) v2(97.5,39.75) v2(98.6,44.45) v2(98.6,43.35) v2(98.6,42.25) v2(98.6,41.05) v2(98.6,40.05)
SR-FET-D: length 5.8
  TOP w0.254: R29.2 87.6,49.1 87.6,48.75 88.8,47.55 88.8,45.55 88.5,45.25 88.3,45.25
SR-FET-G: length 3.2
  TOP w0.254: R23.2 90.2,47.34 90.28,47.26 Q3.4 90.61,46.33 R24.2
TX-AUX-RD1: length 1.7
  BOTTOM w0.5: D3.A 62.17,57.92 R5.1
TX-AUX-RD2: length 1.8
  BOTTOM w0.5: D13.A 54.24,57.57 54.17,57.5 R41.1
TXR-AUX1: length 31.3
  TOP w0.5: J2.4 71.33,40.09 72.2,40.95 72.2,48.15 65.04,55.31 v1(64.16,55.31) v1(63.36,55.31)
  BOTTOM w0.5: T1.5 57.77,53.8 57.18,54.4 C36.1 57.24,55.31 R5.2 v1(63.36,55.31) v1(64.16,55.31)
TXR-AUX1_16126607: length 26
  TOP w0.5: v1(49.4,21.95) R7.2
  SIGNAL LAYER 2 w0.5: J3.4 71.33,25.49 70.4,24.55 58.4,24.55 55.8,21.95 v1(49.4,21.95) v1(48.8,21.95)
  BOTTOM w0.5: v1(49.4,21.95) v1(48.8,21.95)
TXR-AUX-NPN-B1: length 3.5
  BOTTOM w0.5: D1.K 62.07,64.25 R6.2 63.52,64.12 63.75,63.9
TXR-AUX-NPN-C1: length 8
  BOTTOM w0.5: Q2.3 64.14,61.25 D3.C 62.5,62.48 R6.1 61.93,62.78 61.65,62.5 C8.1
TXR-AUX-NPN-E: length 1.9
  BOTTOM w0.5: 65.65,63.9 65.65,65.1 R10.2
TYPE-C_GND: length 39.2
  TOP w0.55: C25.2 90.9,57.85 v1(90.9,58.65) 90.9,60.75 v1(91.37,61.22)
  TOP w0.8: D11.A 98.44,57.2 D10.A v1(98.44,58.05) D9.A D8.A
  SIGNAL LAYER 1 w0.5: v1(98.44,58.05) 98.14,58.35 94.1,58.35 93.1,59.35 93.1,60.16 92.04,61.22 v1(91.37,61.22)
  BOTTOM w0.254: R39.1 92.5,51.88 92.5,50.95 92.1,50.55 90.79,50.55 R38.2
  BOTTOM w0.5: J1.B1 91.91,54.86 91.5,54.45 ; v1(90.9,58.65) 90.9,60.75 v1(91.37,61.22) 92.23,61.22 92.39,61.06 J1.A1
  BOTTOM w0.8: R39.1 91.5,52.92 91.5,54.45 90.9,55.05 v1(90.9,58.65) ; v1(91.37,61.22) 91.03,61.22 90.22,62.03 C32.1 90.23,62.45 R36.2
VCLAMP-RCD: length 7
  TOP w1: C10.2 58.35,35.65 R16.2 R13.2 R14.2
VDC_IN: length 35.2
  TOP w1: C10.1 58.2,43.65 59,44.45 R15.1 ; T1.2 59.35,48.44 60.5,47.3 R15.1 ; R15.1 R12.1
  BOTTOM w1: R44.1 44.95,40.55 45.1,40.7 L3.2 48.5,43.6 C2.1 C6.1 51.45,43.8 C5.1 56.09,48.44 T1.2
N14642334: length 13.4
  TOP w1: CX2.1 36.6,49.45 EF9.1
  BOTTOM w1: D4.A 38.3,46.3 EF9.1 ; BD1.3 38,56.85 CX2.1
N14642346: length 33.7
  TOP w1: EF10.1 38.05,41.2 41.45,44.6 41.45,54 38,57.45 CX2.2
  BOTTOM w1: CX2.2 38.15,65.7 BD1.2 ; D2.A 38.5,41.2 EF10.1
N15949532: length 1.4
  TOP w0.254: U2.24 83.38,55.53 83,55.15 82.66,55.15 C18.2
N15949534: length 1.2
  TOP w0.254: C18.1 82.56,56.03 U2.23
N15949698: length 23.9
  SIGNAL LAYER 2 w1: J1.MH3 J1.MH4
  BOTTOM w0.8: J1.MH2 97.55,62.34 93.5,62.34 93.39,62.45 C32.2 R36.1
  BOTTOM w1: J1.MH3 J1.S2 97.48,56.63 97.48,59.29 J1.S1 J1.MH2 J1.MH1
N15949882: length 17.5
  TOP w0.254: R31.1 91.82,49.75 91.36,49.75 91.11,49.5 v3(91.11,49.45) ; U2.19 v3(83.58,58.6)
  SIGNAL LAYER 2 w0.254: v3(91.11,49.45) 90.41,48.75 87.1,48.75 83.21,52.64 83.21,58.23 v3(83.58,58.6)
N15963322: length 2.3
  TOP w0.254: T2.2 67.81,13.28 R21.2
N15963346: length 1.5
  TOP w0.254: R20.2 C13.2
N15963350: length 3.5
  TOP w0.254: C13.1 70.88,14.43 71.5,15.05 T2.1
N15983010: length 9.3
  TOP w1: R15.2 R12.2 R13.1 R16.1 60.5,38.95 R15.2
N15985596: length 3.4
  BOTTOM w0.25: D12.A 64.77,38.62 64.67,38.52 R17.2 63.57,38.75 C38.1
N16013994: length 7.2
  BOTTOM w0.25: Q1.G 64.56,40.65 C37.1 R1.2 60.93,40.58 C38.2 60.83,38.65 R45.2
N16032372: length 3.1
  TOP w1: R14.1 65.1,41.23 D6.C
N16078751: length 1.5
  BOTTOM w0.5: D13.C R43.1
N16079880: length 7
  BOTTOM w0.5: T1.1 55.23,51.31 52.83,53.71 R41.2
N16095646: length 12.2
  TOP w1: EF11.1 25.4,41.2 22.48,44.12 LF1.2
N16095654: length 26.5
  TOP w1: v1(13.6,44.12) v1(12.5,44.12) LF1.3
  BOTTOM w1: EF12.1 27.25,46.3 25.07,44.12 v1(13.6,44.12) v1(12.5,44.12)
N16166937: length 2.1
  BOTTOM w0.25: R40.2 65.3,35.45 65.57,35.72 D12.C

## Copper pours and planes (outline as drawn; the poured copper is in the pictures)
VBUS_C on TOP: 90.7,55.55 90.7,51.55 91.6,50.65 92.5,50.65 93,50.15 93,49.35 93.2,49.15 94.1,49.15 94.4,48.85 95.4,48.85 95.6,49.05 95.6,52.25 95.1,52.75 92.7,52.75 92.1,53.35 92.1,54.15 93.8,55.85 93.8,59.35 92.6,60.55 91.7,60.55 91.5,60.35 91.5,58.75 91.7,58.55 92.2,58.55 92.4,58.35 92.4,56.65 92.2,56.45 91.6,56.45
VBUS_IN on TOP (solid shape): 97.65,48.21 95.94,48.21 95.94,50.5 97.65,50.5
VBUS_IN on TOP: 95.9,50.65 95.9,48.05 95.6,47.75 93.4,47.75 92.7,47.05 92.7,43.75 91.3,42.35 91.3,38.05 92.2,37.15 93.8,37.15 94.2,37.55 94.2,42.25 96.5,44.55 96.5,46.85 97,47.35 98.9,47.35 99.2,47.65 99.2,50.45 98.7,50.95 96.2,50.95
VBUS_IN on TOP: 82.3,38.15 85.5,38.15 86.4,37.25 86.4,33.15 86.1,32.85 84.3,32.85 83.8,33.35 83.8,34.05 81.8,36.05 81.8,37.65
VBUS_IN on BOTTOM: 79.5,52.55 79.5,51.05 80.1,50.45 84.4,50.45 85.8,49.05 85.8,42.05 81.8,38.05 81.8,36.05 82.3,35.55 84.3,35.55 88.3,39.55 91.5,39.55 95.2,43.25 95.2,47.05 94.8,47.45 90.3,47.45 85.5,52.25 84.4,52.25 83.5,53.15 80.1,53.15
BD-OUT on TOP: 45.3,47.45 44.5,46.65 44.5,45.65 44.7,45.45 46,45.45 47.2,46.65 47.2,56.95 46,58.15 46,61.65 48.5,64.15 49.2,64.15 49.6,64.55 49.6,65.55 49.1,66.05 47.3,66.05 44.2,62.95 44.2,56.95 45.3,55.85
PE_GND on TOP: 49.5,43.25 52.9,39.85 53.6,39.85 54.1,40.35 54.1,41.25 50.9,44.45 50.9,49.45 54.1,52.65 55.73,52.65 56.13,53.05 56.13,54.62 55.4,55.35 55.4,63.65 55.6,63.85 56.3,63.85 56.6,64.15 56.6,64.35 56.4,64.55 55,64.55 54.5,64.05 54.5,55.65 52.4,53.55 51.6,53.55 51.3,53.85 51.3,59.55 50.1,60.75 48.5,60.75 48,60.25 48,59.55 49.5,58.05
PE_GND1 on TOP: 61.5,21.05 53.4,21.05 53.1,20.75 53.1,18.45 53.4,18.15 55.2,18.15 55.5,18.45 55.5,19.45 55.8,19.75 59.5,19.75 61.4,17.85 62.5,17.85 63,17.35 64.1,17.35 64.5,17.75 64.5,22.05 64.35,22.2 63.05,22.2 62.4,22.85 61.8,22.85 61.7,22.75 61.7,21.25
PE_GND1 on BOTTOM: 64.4,21.05 57.9,21.05 57.5,20.65 57.5,18.46 59.01,16.95 63.6,16.95 64.6,17.95 64.6,20.85
PE_GND1 on SIGNAL LAYER 1: 54.4,26.45 63.5,26.45 64.6,25.35 64.6,18.85 63.5,17.75 58.5,17.75 54.1,22.15 54.1,26.15
PRI-FET-S on TOP: 71,46.85 68,46.85 67.6,46.45 67.6,41.45 68.6,40.45 69.8,40.45 71.3,41.95 71.3,46.55
PRI-FET-S on BOTTOM: 73.5,48.35 63.6,48.35 61.8,46.55 59,46.55 58.4,45.95 58.4,41.55 58.6,41.35 63.3,41.35 63.8,41.85 66.2,41.85 66.5,41.55 66.5,39.95 66.9,39.55 73.5,39.55 74,40.05 74,47.85
SE_GND on TOP: 90.7,45.85 89.9,45.85 89.6,45.55 89.6,42.65 89.3,42.35 89.3,38.65 88.6,37.95 87.6,37.95 87.1,37.45 87.1,33.35 87.4,33.05 97.4,33.05 98.1,33.75 98.1,36.15 96.9,37.35 96.9,38.55 97.5,39.15 98.9,39.15 99.2,39.45 99.2,46.85 99.1,46.95 97.5,46.95 97.1,46.55 97.1,44.35 94.8,42.05 94.8,36.95 94.2,36.35 92.1,36.35 90.91,37.54 90.9,42.45 92.3,43.85 92.3,45.35 92.2,45.45 91.1,45.45
SE_GND on BOTTOM: 88.5,38.95 84.2,34.65 80.5,34.65 80.2,34.35 80.2,33.45 80.6,33.05 96.1,33.05 96.4,33.35 96.4,38.75 97,39.35 98.5,39.35 99.2,40.05 99.2,48.15 97.6,49.75 93.8,49.75 93.3,49.25 91.7,49.25 91.6,49.15 91.6,48.25 91.8,48.05 95,48.05 95.8,47.25 95.8,42.95 91.8,38.95
SE_GND on SIGNAL LAYER 1: 79.7,66.15 79.7,54.65 80.1,54.25 84.5,54.25 90.7,48.05 94.8,48.05 95.7,47.15 95.7,42.95 94.8,42.05 94.8,40.15 95.7,39.25 98.7,39.25 99.2,39.75 99.2,48.15 97.6,49.75 92.1,49.75 90.5,51.35 90.5,66.05 89.8,66.75 80.3,66.75
SE_GND on SIGNAL LAYER 2: 89.6,45.75 91.4,45.75 92.3,44.85 92.3,43.45 91,42.15 91,33.35 90.7,33.05 87.5,33.05 87.1,33.45 87.1,37.65 87.6,38.15 88.1,38.15 88.9,38.95 88.9,45.05
SR-FET-D on TOP (solid shape): 88.63,42.48 84.17,42.48 84.17,47.03 88.63,47.03
SR-FET-D on TOP: 81.6,49.45 81.6,48.15 84,45.75 84,40.65 84.3,40.35 85.8,40.35 85.9,40.45 85.9,42.05 88.4,44.55 88.4,46.45 84.8,50.05 82.2,50.05
SR-FET-SNUB on TOP: 84,39.75 84,38.65 84.1,38.55 87.7,38.55 88.1,38.95 88.1,41.05 87.8,41.35 86.6,41.35 86.3,41.05 86.3,40.25 86.1,40.05 84.3,40.05
N15949698 on BOTTOM: 92.8,61.75 96,61.75 96.5,61.25 96.5,54.55 96,54.05 96,53.45 96.5,52.95 98.6,52.95 98.8,53.15 98.8,62.55 98.3,63.05 92.8,63.05 92.6,62.85 92.6,61.95

Small or netless copper shapes (teardrops, artwork), in the pictures only: 1 on TOP

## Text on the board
BOTTOM: CY-SD1124A REV03 SECONDARY SIDE
Ref Des/Assembly Bottom: SECONDARY SIDE | 45W SOLUTION DEMO BOARD | CY-SD1124A PAG1S+PAG1P | ASSEMBLY DRAWING | 620-XXXXX-XX
Board Geometry/Soldermask Bottom: CY-SD1124A REV03 SECONDARY SOLDER MASK
Ref Des/Silkscreen Bottom: REV03 | CY-SD1124A | PAG1S+PAG1P 45W | SOLUTION DEMO KIT | CY-SD1124A REV03 SECONDARY SILKSCREEN
User.Comments: 12/03/21 | HSUB | SAND
TOP: CY-SD1124A REV03 PRIMARY SIDE
Ref Des/Assembly Top: A | PRIMARY SIDE
Board Geometry/Soldermask Top: CY-SD1124A REV03 SOLDER MASK PRIMARY SIDE
Ref Des/Silkscreen Top: A | C | CY-SD1124A | REV03 | CY-SD1124A REV03 PRIMARY SILKSCREEN
SIGNAL LAYER 1: CY-SD1124A REV03 INNER LAYER1
SIGNAL LAYER 2: CY-SD1124A REV03 INNER LAYER2
PAGE_OUTLINE: REV | 198 CHAMPION COURT | SAN JOSE, CA 95134 | (408) 943-2600 | 02/09/20 | 04/01/21 | 12/03/21 | INITIAL RELEASE | REVISION 2 | REVISION 3 | 1 | 2 | 3 | RAAH | HSUB | 45W SOLUTION DEMO BOARD | CY-SD1124A PAG1S+PAG1P | C | 03
DIMENSION: X5 | X4 | 48 mils | +/-0.1 | 1.2 mm | +/-10% | LAYER 4 BOTTOM,2 OZ | PREPERG | LAYER 3 SIGNAL LAYER,2 OZ | LAYER 2 BOTTOM,2 OZ | LAYER 1 TOP,2 OZ | LAYER 2 GROUND LAYER,2 OZ | CORE | PRIMARY SIDE | SECONDARY SIDE | ONLY THIS BOARD IS 2 LAYER BOARD | REMAINING 3 ARE 4 LAYER BOARDS | A. FR4 OR EQUIVALENT MATERIAL(HIGH ELECTRONIC RELIABILITY) MUST CONFIRM TO UL94V-0 | 1. RoHS COMPLIANT CERTIFICATION OR MATERIAL DECLARATION REQUIRED. | 2. MATERIAL: | B. USE HTE COPPER, AS SPECIFIED IN THE CROSS SECTION DIAGRAM. | 3. DRILLING: | A. DIAMETERS IN DRILL TABLE ARE FINISHED HOLE SIZES +/-.003 tol. | UNLESS OTHERWISE SPECIFIED IN DRILL TABLE. | B. TEARDROP ALLOWED ON ENTRY OF VIA ON EVERY TRACE LAYER. | 4. PLATING: | COPPER PLATING IN THRU-HOLES .001 min. | 5. MARKING: | A. SILKSCREEN IN WHITE NON-CONDUCTIVE EPOXY INK ON PRIMARY SIDE OF THE | BOARD OR BOTH SIDES IF APPLICABLE. | B. FABRICATOR TO PLACE DATE CODE, LOGO AND RoHS COMPILANT SYMBOL IN SILKSCREEN ON SECONDARY SIDE. | 6. FINAL FABRICATION: | A. SOLDRMASK PRIMARY AND SECONDARY SIDE OF BOARD USING LIQUID PHOTOIMAGABLE | MASK MATERIAL OVER BARE COPPER. PER IPC-SM-840. MASK ARTWORKS PROVIDED | ARE 1:1. SOLDERMASK COLOR *BLUE** | 7. FINISH: | A. SHALL BE ELECTROLESS NIKEL / IMMERSION GOLD(ENIG). | B. NICKEL THICKNESS: 100-200 MICROINCHES. | C. GOLD THICKNESS: 3-10 MICROINCHES. | 8. BOARDS SHALL BE PURCHASED FROM UL RECOGNIZED VENDORS ONLY. | FLAMABILITY RATING (94-V0). | 9. MANUFACTURE BOARD TO BE IN ACCORDANCE WITH PERFORMANCE STANDARD | IPC-6011/6012 CLASS 2 BOARD TO BE INSPECTED PER IPC-600-A CLASS 2. | 10.MAXIMUM WRAP OR TWIST SHALL NOT EXCEED .007 in/in. | 12.ENSURE ALL THE VIA HOLES ARE FILLED WITH SOLDER MASK TO ENSURE GOOD QUALITY OF SILK SCREEN PRINT. | 13.CARE MUST BE TAKEN TO AVOID OVER ETCHING OF COPPER ON PADS. | 14.THIS IS HIGH VOLTAGE BOARD.SO DON'T ADD THIEVING COPPER IN VOID AREA FOR COPPER BALANCE. | 11.TESTING: | A. FABRICATOR TO ADD TEST STRUCTURES OR CUPONS AS NEEDED. | B. T-LINE IMPEDENCE TO BE TESTED OR GUARANTEE WITHIN 10% IF SPECIFIED IN | 15.MANUFACTURE BOARD TO BE IN ACCORDANCE WITH CTI STANDARD OF 400>CTI<600 | C. OVERALL METAL TO METAL THICKNESS AS SPECIFIED IN THE CROSS SECTION. | THE CROSS SECTION.  TOLERANCE TO BE +/-10% UNLESS OTHERWISE SPECIFIED. | NOTES:(UNLESS OTHERWISE SPECIFIED)
User.15: CY-SD1124A REV03 PRIMARY ASSEMBLY
User.23: CY-SD1124A REV03 SECONDARY ASSEMBLY
User.41: CY-SD1124A REV03 PRIMARY SOLDERPASTE
User.42: CY-SD1124A REV03 SECONDARY SOLDERPASTE
User.45: FIGURE | FINISHED_SIZE | 0.254 | 0.381 | 0.508 | 0.7 | 0.8 | 0.904 | 0.95 | 1.02 | 1.1 | 0.5999 | 1.5999x0.5999 | 1.7x1.4 | 1.8999x0.5999 | 2.5x2.0 | 0.8499x0.5999 | ROTATION | - | 0.000 | 45.000 | 90.000 | DRILL CHART: TOP to BOTTOM | ALL UNITS ARE IN MILLIMETERS | TOLERANCE_DRILL | +0.0762/-0.0762 | +0.0759/-0.0759 | TOLERANCE_TRAVEL | PLATED | NON-PLATED | QTY | 88 | 51 | 7 | 2 | 18 | 4 | 6 | 8 | 1 | 5 | DO NOT DISCLOSE TO OR DUPLICATE FOR | PROPRIETARY INFORMATION THAT IS | CYPRESS SEMICONDUCTOR PROPERTY. | OTHERS EXCEPT AS AUTHIRIZED BY CYPRESS. | THIS DOUCUMENT CONTAINS CONFIDENTAL, | REV | DWG NO | FSCM NO | SIZE | SCALE: | SHEET: | DATE | SIGNATURES | ENGRG : | ISSUED | DRAWN : | CHECKED : | ANGLES +/- 2 | UNLESS OTHERWISE SPECIFIED | PROJECTIONS | DIMENSIONS ARE IN INCHES | TOLERANCES ON; | 2 PL DECIMALS +/- .010 | 3 PL DECIMALS +/- .005 | THIRD ANGLE | 06/02/17 | 12/03/21 | 2 OF 2 | FAB | PRVE | HUSAIN | HITS | SEMICONDUCTOR | REVISIONS | CYPRESS PROPRIETARY | APPROVED | 04/01/21 | 02/09/20 | DESCRIPTION | RAAH | HUSA | 198 CHAMPION COURT | SAN JOSE, CA 95134 | (408) 943-2600 | 1/1 | REVISION 2 | REVISION 3 | INITIAL RELEASE | 3 | FABRICATION DRAWING | ASSEMBLY DRAWING | CYPRESS | 620-XXXXX-XX | 610-XXXXX-XX | 03 | C | C201 | C200 | L200
